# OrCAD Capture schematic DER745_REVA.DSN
size C
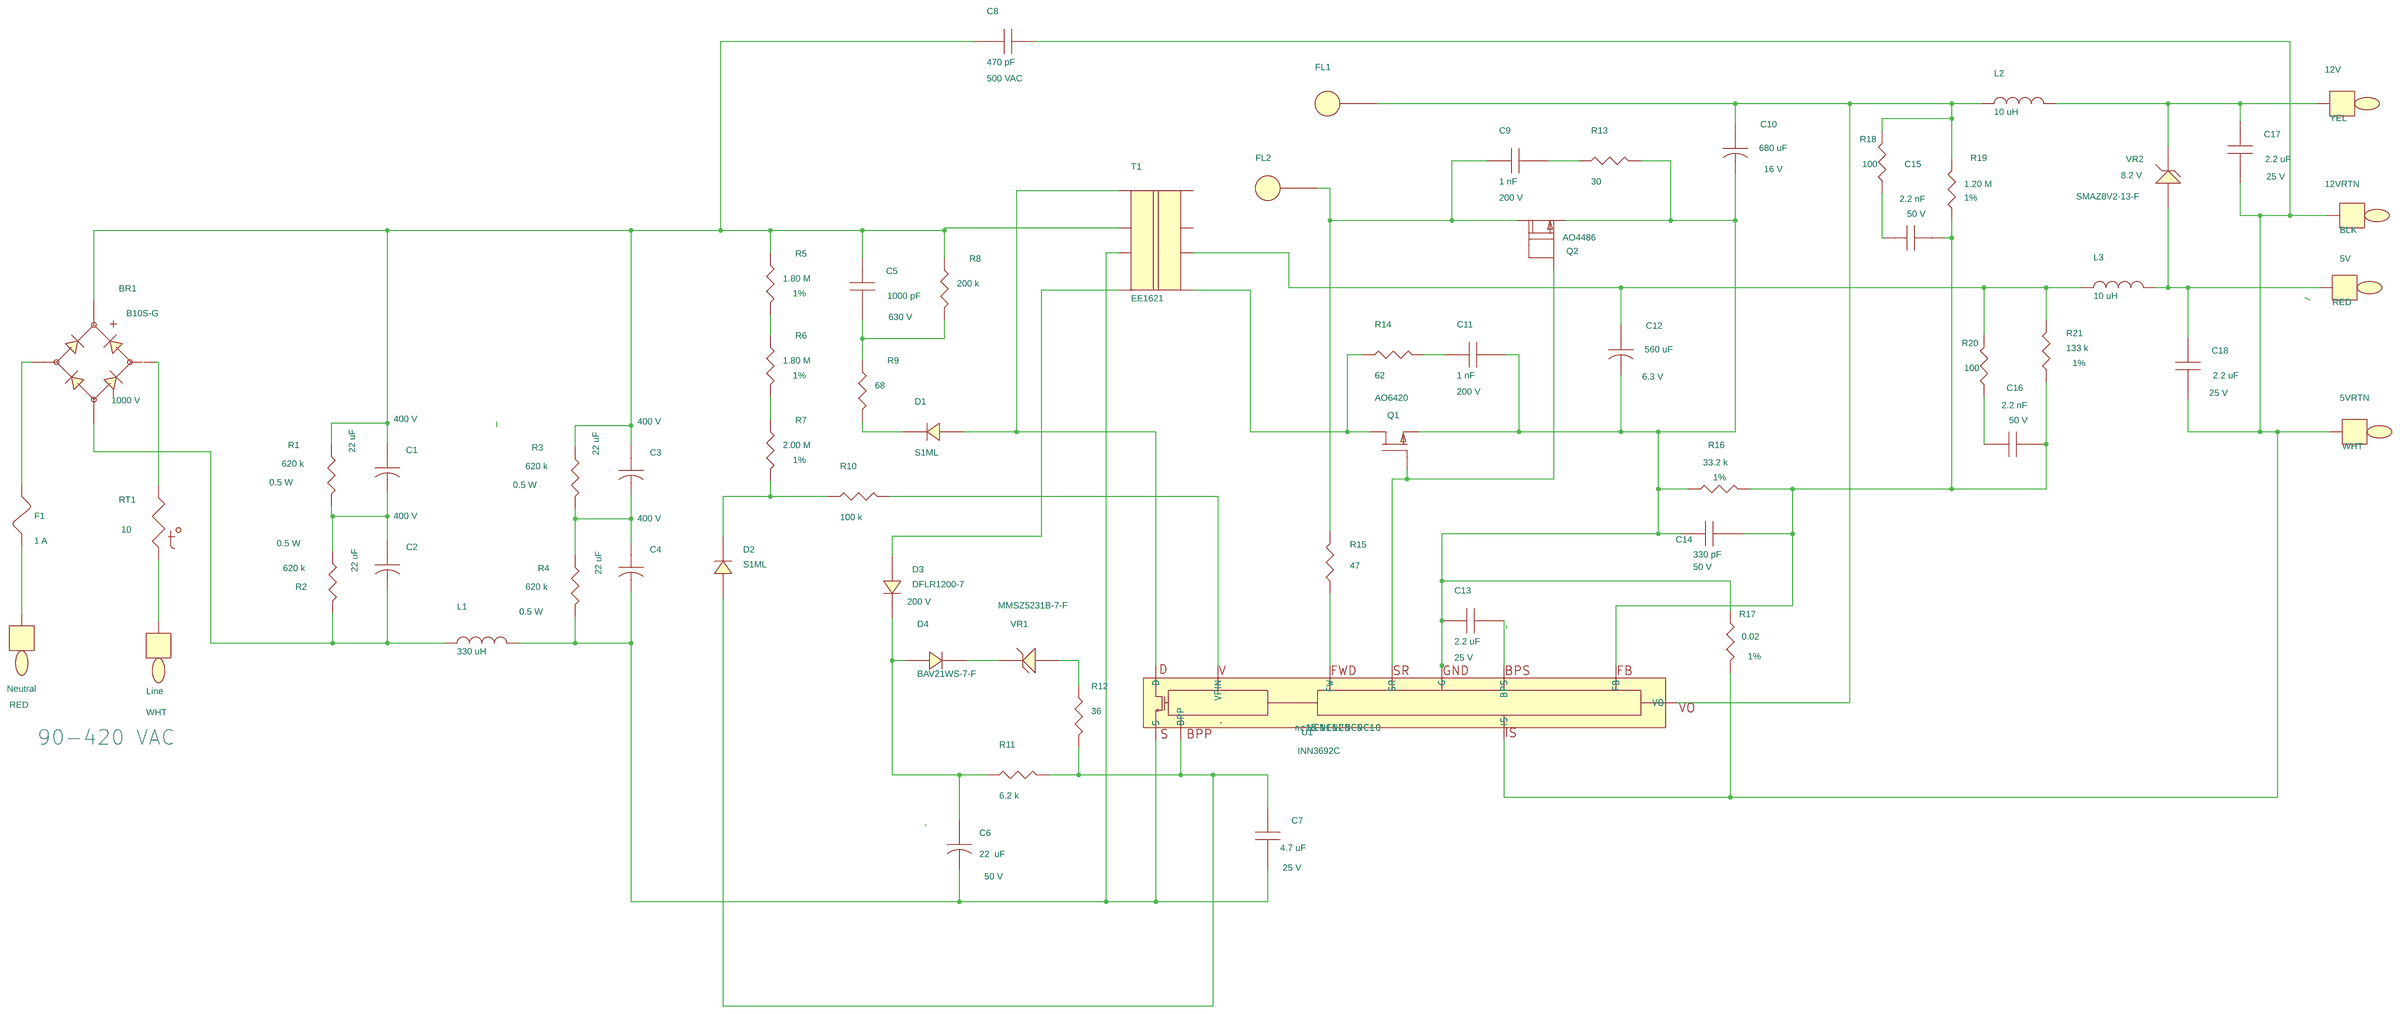
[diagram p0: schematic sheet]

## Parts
5V  RED  [pitpkeystone100x100]
5VRTN  WHT  [pitpkeystone100x100]
12V  YEL  [pitpkeystone100x100]
12VRTN  BLK  [pitpkeystone100x100]
BR1  B10S-G  [pismsoic4]
C1  22 uF  [pipolcapclyd500ls200040]
C2  22 uF  [pipolcapclyd500ls200040]
C3  22 uF  [pipolcapclyd500ls200040]
C4  22 uF  [pipolcapclyd500ls200040]
C5  1000 pF  [pismc1206]
C6  22  uF  [pipolcapclyd200ls80030]
C7  4.7 uF  [pismc0805]
C8  470 pF  [pi_np_cap280x300ls300d030]
C9  1 nF  [pismc0805]
C10  680 uF  [pipolcapcyld400ls200040]
C11  1 nF  [pismc0805]
C12  560 uF  [pipolcapcyld315ls138d030]
C13  2.2 uF  [pismc0805]
C14  330 pF  [pismc0603]
C15  2.2 nF  [pismc0603]
C16  2.2 nF  [pismc0603]
C17  2.2 uF  [pismc1206]
C18  2.2 uF  [pismc1206]
D1  S1ML  [pi_sm_sod-123_12]
D2  S1ML  [pi_sm_sod-123_12]
D3  DFLR1200-7  [pismddflr120012]
D4  BAV21WS-7-F  [pismsod323]
F1  1 A  [pi_rst_microfuse]
FL1  Hole_30mils  [pi_hole_30mil]
FL2  Hole_30mils  [pi_hole_30mil]
L1  330 uH  [pichoketokinvd345h453ls197d030]
L2  10 uH  [pi_choke_tokin_1]
L3  10 uH  [pi_choke_tokin_1]
Line  WHT  [pitpkeystone100x100]
Neutral  RED  [pitpkeystone100x100]
Q1  AO6420  [pismsot236_short1256]
Q2  AO4486  [pismso8]
R1  620 k  [pi12wvresd180ls150d040]
R2  620 k  [pi12wvresd180ls150d040]
R3  620 k  [pi12wvresd180ls150d040]
R4  620 k  [pi12wvresd180ls150d040]
R5  1.80 M  [pismr1206]
R6  1.80 M  [pismr1206]
R7  2.00 M  [pismr1206]
R8  200 k  [pismr1206]
R9  68  [pismr1206]
R10  100 k  [pismr0603]
R11  6.2 k  [pismr0603]
R12  36  [pismr0603]
R13  30  [pismr0805]
R14  62  [pismr0805]
R15  47  [pismr0603]
R16  33.2 k  [pismr0603]
R17  0.02  [pismr0805]
R18  100  [pismr0603]
R19  1.20 M  [pismr0603]
R20  100  [pismr0603]
R21  133 k  [pismr0603]
RT1  10  [pi_rad_276DX197T_ls100d025]
T1  EE1621  [pi_bobbin_ee1621_8p]
U1  INN3692C  [pi_ic_insop_24d]
VR1  MMSZ5231B-7-F  [pi_sm_sod-123_12]
VR2  SMAZ8V2-13-F  [pismdo214ac12]

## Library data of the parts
5V Neutral = TESTPOINT: Part Number: 35-00080-00
5VRTN Line = TESTPOINT: Part Number: 35-00081-00
12V = TESTPOINT: Part Number: 35-00404-00
12VRTN = TESTPOINT: Part Number: 35-00079-00
BR1 = DIODE_BRIDGE_~~+-: ALT_SYMBOLS: pi_sm_soic4_slot; Disp_Voltage: 1000 V; FPLIST: pismsoic4,pi_sm_soic4_slot; Part Number: 15-00818-00
C1-C4 = CAP_POL: ALT_SYMBOLS: pipolcapclyd500ls200040630lh; Disp_Voltage: 400 V; FPLIST: pipolcapclyd500ls200040,pipolcapclyd500ls200040630lh; Part Number: 20-08737-00; Voltage: 400 V
C5 = CAP_NP: Disp_Voltage: 630 V; Part Number: 20-08616-00; Voltage: 630 V
C6 = CAP_POL: ALT_SYMBOLS: pipolcapclyd200ls80030h; Disp_Voltage: 50 V; FPLIST: pipolcapclyd200ls80030,pipolcapclyd200ls80030h; Part Number: 20-00950-00; Voltage: 50 V
C7 = CAP_NP: Disp_Voltage: 25 V; Part Number: 20-09137-00; Voltage: 16 V
C8 = CAP_NP: Disp_Voltage: 500 VAC; Part Number: 20-08697-00; Voltage: 500 VAC
C9 C11 = CAP_NP: Disp_Voltage: 200 V; Part Number: 20-00737-00; Voltage: 200 V
C10 = CAP_POL: Disp_Voltage: 16 V; Part Number: 23-00061-00; Voltage: 16V
C12 = CAP_POL: ALT_SYMBOLS: pipolcapcyld315ls138d030h; Disp_Voltage: 6.3 V; FPLIST: pipolcapcyld315ls138d030,pipolcapcyld315ls138d030h; Part Number: 20-09041-00; Voltage: 6.3 V
C13 = CAP_NP: Disp_Voltage: 25 V; Part Number: 20-08603-00; Voltage: 25 V
C14 = CAP_NP: Disp_Voltage: 50 V; Part Number: 20-08676-00; Voltage: 50 V
C15 C16 = CAP_NP: Disp_Voltage: 50 V; Part Number: 20-08677-00; Voltage: 50 V
C17 C18 = CAP_NP: Disp_Voltage: 25 V; Part Number: 20-01034-00; Voltage: 25 V
D1 D2 = DIODE: Part Number: 15-01027-00
D3 = DIODE: Disp_Voltage: 200 V; Part Number: 15-01019-00
D4 = DIODE: Part Number: 15-00385-00
F1 = FUSE: ALT_SYMBOLS: pirstmicrofusehoz; FPLIST: pi_rst_microfuse,pirstmicrofusehoz; Part Number: 40-00053-00
FL1 FL2 = FlyingLead: Part Number: 35-00284-00
L1 = INDUCTOR: Part Number: 30-00077-00
L2 L3 = INDUCTOR: Part Number: 30-00461-00
Q1 = FET_N_DGS: Part Number: 50-00166-00
Q2 = FET_N_SGD_123_4_5678: Part Number: 50-00254-00
R1-R4 = R: ALT_SYMBOLS: pi12wvresd180ls200d040,pi12wvresd180ls250d040,pi12wresd180ls675d040; Disp_Power: 0.5 W; FPLIST: pi12wvresd180ls150d040,pi12wvresd180ls200d040,pi12wvresd180ls250d040,pi12wresd180ls675d040; Part Number: 05-02742-00
R5 R6 = R: Disp_Tol: 1%; Part Number: 05-03155-00
R7 = R: Disp_Tol: 1%; Part Number: 05-03156-00
R8 = R: Part Number: 05-01407-00
R9 = R: Part Number: 05-01324-00
R10 = R: Part Number: 05-01736-00
R11 = R: Part Number: 05-01707-00
R12 = R: Part Number: 05-01653-00
R13 = R: Part Number: 05-01482-00
R14 = R: Part Number: 05-01490-00
R15 = R: Part Number: 05-01656-00
R16 = R: Disp_Tol: 1%; Part Number: 05-03234-00
R17 = R: Disp_Tol: 1%; Part Number: 05-05450-00
R18 R20 = R: Part Number: 05-01664-00
R19 = R: Disp_Tol: 1%; Part Number: 05-03142-00
R21 = R: Disp_Tol: 1%; Part Number: 05-01186-00
RT1 = THERMISTOR: Part Number: 90-00047-00
T1 = BEE16_8P_GENERIC: Part Number: 25-01044-00
U1 = DEV_Inno3EP: Part Number: 10-01045-00
VR1 = DIODE_ZENER: Part Number: 15-01081-00
VR2 = DIODE_ZENER: Disp_Voltage: 8.2 V; Part Number: 15-01237-00

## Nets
NC8: U1.8(NC8)
NC9: U1.9(NC9)
NC10: U1.10(NC10)
NC11: U1.11(NC11)
NC12: U1.12(NC12)
NC15: U1.15(nc15)
N11050040: 12V.1 C17.1 L2.2 VR2.1
N11050316: BR1.3 C1.1 C3.1 C5.1 C8.2 R1.1 R3.1 R5.1 R8.1 T1.2
N11050566: C5.2 R8.2 R9.1
N11050744: BR1.1 F1.2
N11050756: BR1.2 RT1.1
N11050878: D1.1 R9.2
N11050972: C14.2 C15.2 C16.2 R16.2 R19.1 R21.1 U1.3(FB)
N11051112: D1.2 T1.1 U1.24(D)
N11051256: R15.1 U1.7(FW)
N11051362: C6.1 D3.1 D4.2 R11.1
N11051472: D4.1 VR1.1
N11051658: C7.1 D2.2 R11.2 R12.2 U1.14(BPP)
N11051742: C4.2 C6.2 C7.2 L1.2 R4.2 T1.3 U1.16(S)
N11051898: Line.1 RT1.2
N11051902: F1.1 Neutral.1
N11062996: C9.1 FL2.1 Q2.5(D) R15.2
N11063539: C10.1 FL1.1 L2.1 R18.2 R19.2 U1.6(VO)
N11067713: R10.2 U1.13(VPIN)
N11070094: 5VRTN.1 12VRTN.1 C8.1 C17.2 C18.2 R17.2 U1.1(IS)
N11075733: C11.1 R14.2
N11083581: C10.2 C11.2 C12.2 C13.1 C14.1 Q1.4(S) Q2.1(S) R13.2 R16.1 R17.1 U1.2(G)
N11083861: Q1.3(G) Q2.4(G) U1.5(SR)
N11101991: C12.1 L3.1 R20.2 R21.2 T1.6
N11104379: R12.1 VR1.2
N11115969: C9.2 R13.1
N11124964: D3.2 T1.4
N11129285: Q1.1(D) R14.1 T1.5
N11132220: C13.2 U1.4(BPS)
N11135486: C15.1 R18.1
N11135939: 5V.1 C18.1 L3.2 VR2.2
N11142568: C16.1 R20.1
N11149792: BR1.4 C2.2 L1.1 R2.1
N11149826: C1.2 C2.1 R1.2 R2.2
N11150103: C3.2 C4.1 R3.2 R4.1
N11155318: R5.2 R6.1
N11155322: R6.2 R7.1
N11155751: D2.1 R7.2 R10.1

Not connected (* = marked no-connect by the designer): Q2 2(S2) 3(S3) 6(D6) 7(D7) 8(D8); T1 7 8

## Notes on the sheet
- 90-420 VAC
